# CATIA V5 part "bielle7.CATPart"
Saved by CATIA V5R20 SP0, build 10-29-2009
Part number: bielle7
Bounding box of the stored display mesh (mm): x 4 to 27, y -90 to -70, z -10 to 50
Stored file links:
  D:\Dropbox\IAO_2012\IAO_2012_991_jambrosino\IAO_2012_991_jambrosino_Catia\Assemblage\bielle7.CATPart
  D:\Dropbox\IAO_2012\IAO_2012_991_jambrosino\IAO_2012_991_jambrosino_Catia\Assemblage\Ass_IAO_991_skl.CATProduct
  D:\Dropbox\IAO_2012\IAO_2012_991_jambrosino\IAO_2012_991_jambrosino_Catia\Assemblage\bielle6.CATPart
  J:\IAO_Mecanisme_991\IAO_Mecanisme_991_CATIA\skl_bielle_7.CATPart
  D:\Dropbox\IAO_2012\IAO_2012_991_jambrosino\IAO_2012_991_jambrosino_Catia\Assemblage\bielle2bis.CATPart
  D:\Dropbox\IAO_2012\IAO_2012_991_jambrosino\IAO_2012_991_jambrosino_Catia\Assemblage\couteau3.CATPart
  J:\IAO_Mecanisme_991\IAO_Mecanisme_991_CATIA\skl_bielle_2.CATPart
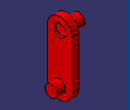
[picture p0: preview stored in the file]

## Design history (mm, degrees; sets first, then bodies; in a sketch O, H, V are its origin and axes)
Set1
  Plane1: linked copy from another document
  DatumPoint1: linked copy from another document
  DatumPoint2: linked copy from another document
  DatumSurface1: linked copy from another document
  DatumPoint3: linked copy from another document
  DatumCurve1: linked copy from another document
  DatumCurve2: linked copy from another document
  DatumPoint4: linked copy from another document
  DatumSurface2: linked copy from another document
  DatumPoint5: linked copy from another document
Body1 (main body)
  Sketch1 on Plane1, origin (20, 0, 0), H (0, 1, 0), V (0, 0, 1)
    line L1 (-70, 40) -> (-70, 0)
    line L2 (-90, 0) -> (-90, 40)
    arc A1 centre (-80, 40) radius 10 from (-70, 40) to (-90, 40) ccw
    point P5 (-80, 40)
    arc A2 centre (-80, 0) radius 10 from (-90, 0) to (-70, 0) ccw
    point P6 (-80, 0)
    circle A3 centre (-80, 40) radius 5
    circle A4 centre (-80, 0) radius 5
    reference projected point E1 (-80, 40) from vertex of DatumPoint1
    reference projected point E2 (-80, 0) from DatumPoint2
    radius A3 = 5
    radius A4 = 5
    radius A1 = 10
    vertical: L1 V, L2 V
    tangency: A1 L1, A2 L1, L2 A2, A1 L2
    coincidence: P5 E1, P6 E2
  Pad1: profile Sketch1, direction (-1, 0, 0), length 6
  Sketch2 on DatumSurface1, origin (22, 0, 0), H (0, 1, 0), V (0, 0, 1)
    circle A1 centre (-80, 0) radius 5
    point P1 (-80, 0)
    reference projected point E1 (-80, 0) from DatumPoint2
    reference projected circle E2 centre (-80, 0) radius 5 from edge of DatumCurve2
    coincidence: P1 E1, A1 E2
  Pad2: profile Sketch2, direction (1, 0, 0), length 5, opposite side length 6
  Sketch3 on end face of Pad1, origin (14, 0, 0), H (0, -1, 0), V (0, 0, 1)
    circle A1 centre (80, 40) radius 5
    point P1 (80, 40)
    reference projected point E1 (80, 40) from DatumPoint4
    reference projected circle E2 centre (80, 40) radius 5 from edge [face of Pad1 from Sketch1.A3 | end face of Pad1]
    coincidence: P1 E1, A1 E2
  Pad3: profile Sketch3, direction (-1, 0, 0), length 10, opposite side length 4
